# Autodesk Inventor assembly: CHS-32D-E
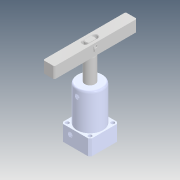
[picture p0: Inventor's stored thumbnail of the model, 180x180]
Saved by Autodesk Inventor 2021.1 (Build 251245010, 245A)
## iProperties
Created: 2020-02
Part Number: CHS-32D-E
Description: STEP AP214
Document SubType Name: Assembly
Designer: user
Title: chs-32d-e_asm.STEP
Revision Number: ÈÎºÎ
Sending System: SolidWorks 2016
Preprocessor: SwSTEP 2.0
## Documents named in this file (6)
- D:\Vault_2016\Projekty\Clamptek\Hydraulic\CHS\CHS-32\Inventor\CHS-32D-E\CHS-32D-E.iam
- D:\Vault_2016\Projekty\Clamptek\Hydraulic\CHS\CHS-32\Inventor\CHS-32D-E\CHS-32-03-E.ipt
- D:\Vault_2016\Projekty\Clamptek\Hydraulic\CHS\CHS-32\Inventor\CHS-32D-E\CHS-32D-02-E_1.ipt
- D:\Vault_2016\Projekty\Clamptek\Hydraulic\CHS\CHS-32\Inventor\CHS-32D-E\CHS-32D-01_1.ipt
- D:\Vault_2016\Projekty\Clamptek\Hydraulic\CHS\CHS-32\Inventor\CHS-32D-E\Öá8µ²È¦.ipt
- D:\Vault_2016\Projekty\Clamptek\Hydraulic\CHS\CHS-32\Inventor\CHS-32D-E\Xiaozhou.ipt
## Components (6 placed, 6 different names)
1. CHS-32-03-E_1
2. CHS-32D-02-E_1_2
3. CHS-32D-01_1_3
4. Öá8µ²È¦_4
5. Xiaozhou_5
6. Öá8µ²È¦_6
